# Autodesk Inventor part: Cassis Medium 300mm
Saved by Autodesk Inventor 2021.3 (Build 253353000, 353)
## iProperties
Created: 2023-09
Part Number: Cassis Medium 300mm
Material: Generic
Document SubType Name: Modeling
Designer: AdminForWorker
Density: 1 g/cm^3
Appearance: Default
Title: Cassis Medium 300mm v3
Author: AdminForWorker
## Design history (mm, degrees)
feature "Body1"
feature "Body2"
feature "Body7"
feature "Body3"
feature "Body4"
feature "Body5"
feature "Body6"
body "Solid1"
body "Solid2"
body "Solid3"
body "Solid4"
body "Solid5"
body "Solid6"
body "Solid7"
